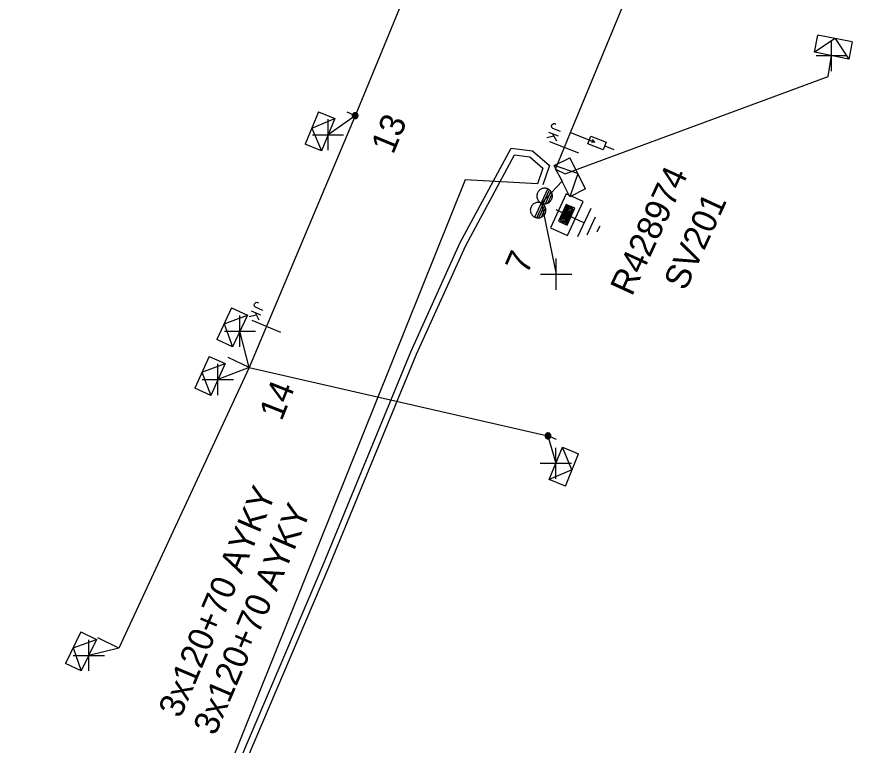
# Model space of a CAD drawing. Extents: x -540247 to -537390, y -1183887 to -1180355.
# Drawn here: x -537727.87 to -537694.26, y -1180525.39 to -1180496.15 of the extents above; entities that cross this region are included whole.
import ezdxf

# ---------------------------------------------------------------- set-up
doc = ezdxf.new("R2010")
doc.units = 0
for name, color, linetype in [('Vrstva 1', 7, 'Continuous'), ('Vrstva 13', 7, 'Continuous'), ('Vrstva 14', 7, 'Continuous'), ('Vrstva 15', 7, 'Continuous'), ('Vrstva 16', 7, 'Continuous'), ('Vrstva 18', 7, 'Continuous'), ('Vrstva 2', 7, 'Continuous'), ('Vrstva 28', 7, 'Continuous'), ('Vrstva 29', 7, 'Continuous'), ('Vrstva 30', 7, 'Continuous'), ('Vrstva 31', 7, 'Continuous'), ('Vrstva 34', 7, 'Continuous'), ('Vrstva 4', 7, 'Continuous'), ('Vrstva 5', 7, 'Continuous'), ('Vrstva 50', 7, 'Continuous'), ('Vrstva 52', 7, 'Continuous'), ('Vrstva 54', 7, 'Continuous'), ('Vrstva 6', 7, 'Continuous'), ('Vrstva 8', 7, 'Continuous'), ('Vrstva 9', 7, 'Continuous')]:
    doc.layers.add(name, color=color, linetype=linetype)

# ---------------------------------------------------------------- blocks, each defined once
blk = doc.blocks.new('NN450')
at = {"layer": 'Vrstva 2'}
for points in [[(0, 0), (-0.003, 0.065), (-0.013, 0.13), (-0.031, 0.193), (-0.054, 0.254), (-0.084, 0.312), (-0.119, 0.367), (-0.161, 0.418), (-0.207, 0.464), (-0.258, 0.505), (-0.313, 0.541), (-0.371, 0.571), (-0.432, 0.594), (-0.495, 0.611), (-0.559, 0.621), (-0.625, 0.625), (-0.69, 0.621), (-0.755, 0.611), (-0.818, 0.594), (-0.879, 0.571), (-0.938, 0.541), (-0.992, 0.505), (-1.043, 0.464), (-1.089, 0.418), (-1.13, 0.367), (-1.166, 0.312), (-1.196, 0.254), (-1.219, 0.193), (-1.236, 0.13), (-1.246, 0.065), (-1.25, 0), (-1.246, -0.066), (-1.236, -0.13), (-1.219, -0.193), (-1.196, -0.255), (-1.166, -0.313), (-1.13, -0.368), (-1.089, -0.419), (-1.043, -0.465), (-0.992, -0.506), (-0.937, -0.542), (-0.879, -0.571), (-0.818, -0.595), (-0.755, -0.612), (-0.69, -0.622), (-0.625, -0.625), (-0.559, -0.622), (-0.495, -0.612), (-0.432, -0.595), (-0.37, -0.571), (-0.312, -0.542), (-0.258, -0.506), (-0.207, -0.465), (-0.161, -0.419), (-0.119, -0.368), (-0.084, -0.313), (-0.054, -0.254), (-0.031, -0.193), (-0.013, -0.13), (-0.003, -0.066), (0, 0)], [(1.25, 0), (1.247, 0.065), (1.237, 0.13), (1.219, 0.193), (1.196, 0.254), (1.166, 0.312), (1.131, 0.367), (1.089, 0.418), (1.043, 0.464), (0.992, 0.505), (0.937, 0.541), (0.879, 0.571), (0.818, 0.594), (0.755, 0.611), (0.691, 0.621), (0.625, 0.625), (0.56, 0.621), (0.495, 0.611), (0.432, 0.594), (0.371, 0.571), (0.312, 0.541), (0.258, 0.505), (0.207, 0.464), (0.161, 0.418), (0.12, 0.367), (0.084, 0.312), (0.054, 0.254), (0.031, 0.193), (0.014, 0.13), (0.004, 0.065), (0, 0), (0.004, -0.066), (0.014, -0.13), (0.031, -0.193), (0.054, -0.255), (0.084, -0.313), (0.12, -0.368), (0.161, -0.419), (0.207, -0.465), (0.258, -0.506), (0.313, -0.542), (0.371, -0.571), (0.432, -0.595), (0.495, -0.612), (0.56, -0.622), (0.625, -0.625), (0.691, -0.622), (0.755, -0.612), (0.818, -0.595), (0.88, -0.571), (0.938, -0.542), (0.992, -0.506), (1.043, -0.465), (1.089, -0.419), (1.131, -0.368), (1.166, -0.313), (1.196, -0.254), (1.219, -0.193), (1.237, -0.13), (1.247, -0.066), (1.25, 0)], [(-1.25, 0), (1.25, 0)], [(-1.23, -0.158), (-0.02, -0.158)], [(-1.161, -0.315), (-0.088, -0.315)], [(-1.033, -0.473), (-0.216, -0.473)], [(0.02, -0.158), (1.23, -0.158)], [(0.089, -0.315), (1.162, -0.315)], [(0.217, -0.473), (1.034, -0.473)]]:
    blk.add_lwpolyline(points, dxfattribs=at)
blk = doc.blocks.new('NN840')
at = {"layer": 'Vrstva 15'}
for points in [[(0.003, 0.619), (0.003, -0.631)], [(-0.745, -0.71), (-0.745, -0.66)], [(-0.538, -0.385), (-0.538, -0.71)], [(-0.332, -0.385), (-0.332, -0.798)], [(-0.332, -0.641), (-0.125, -0.385)], [(-0.263, -0.557), (-0.091, -0.798)], [(-0.73, -0.764), (-0.745, -0.71)], [(-0.657, -0.798), (-0.73, -0.764)], [(-0.627, -0.798), (-0.657, -0.798)], [(-0.558, -0.764), (-0.627, -0.798)], [(-0.538, -0.71), (-0.558, -0.764)]]:
    blk.add_lwpolyline(points, dxfattribs=at)
blk = doc.blocks.new('NN800')
at = {"layer": 'Vrstva 1'}
for points in [[(-0.442, 0.442), (0.442, -0.442)], [(-0.442, -0.442), (0.442, 0.442)]]:
    blk.add_lwpolyline(points, dxfattribs=at)
blk = doc.blocks.new('NN820')
at = {"layer": 'Vrstva 13'}
for points in [[(-0.003, 0.004), (-0.003, -1.049)], [(-0.165, -0.813), (0.165, -0.813)], [(-0.165, -1.473), (-0.165, -0.813)], [(-0.003, -1.049), (-0.062, -0.926)], [(-0.003, -1.049), (0.057, -0.926)], [(0.165, -0.813), (0.165, -1.473)], [(0.165, -1.473), (-0.165, -1.473)], [(-0.003, -1.473), (-0.003, -1.871)]]:
    blk.add_lwpolyline(points, dxfattribs=at)
blk = doc.blocks.new('NN620')
at = {"layer": 'Vrstva 8'}
for points in [[(0.752, 0.004), (-0.748, 0.004)], [(-0.748, 0.004), (-0.748, -0.746)], [(0.752, -0.746), (0.752, 0.004)], [(0.368, -0.18), (-0.376, -0.18)], [(-0.376, -0.18), (-0.376, -0.558)], [(0.321, -0.227), (-0.329, -0.227)], [(-0.329, -0.227), (-0.329, -0.51)], [(0.274, -0.274), (-0.281, -0.274)], [(-0.281, -0.274), (-0.281, -0.463)], [(0.227, -0.321), (-0.234, -0.321)], [(-0.234, -0.321), (-0.234, -0.416)], [(0.227, -0.416), (0.227, -0.321)], [(0.274, -0.463), (0.274, -0.274)], [(0.321, -0.51), (0.321, -0.227)], [(0.368, -0.558), (0.368, -0.18)], [(-0.376, -0.558), (0.368, -0.558)], [(-0.329, -0.51), (0.321, -0.51)], [(-0.281, -0.463), (0.274, -0.463)], [(-0.234, -0.416), (0.227, -0.416)], [(-0.193, -0.369), (0.185, -0.369)], [(-0.748, -0.746), (0.752, -0.746)]]:
    blk.add_lwpolyline(points, dxfattribs=at)
blk = doc.blocks.new('NN630')
at = {"layer": 'Vrstva 9'}
for points in [[(-0.003, -0.7), (-0.703, 0)], [(-0.703, -0.7), (-0.703, 0), (0.697, 0), (0.697, -0.7)], [(-0.003, -0.7), (0.697, 0)], [(-0.703, -0.7), (0.697, -0.7)]]:
    blk.add_lwpolyline(points, dxfattribs=at)
blk = doc.blocks.new('NN810')
at = {"layer": 'Vrstva 14'}
for points in [[(0.004, -0.64), (0.004, -1.89)], [(0.629, -1.89), (-0.621, -1.89)], [(0.388, -2.2), (-0.399, -2.2)], [(0.004, -2.515), (-0.124, -2.515)], [(0.137, -2.515), (0.004, -2.515)]]:
    blk.add_lwpolyline(points, dxfattribs=at)
blk = doc.blocks.new('NN500')
at = {"layer": 'Vrstva 2'}
for points in [[(-0.001, -0.235), (0.023, -0.234), (0.048, -0.23), (0.071, -0.224), (0.094, -0.215), (0.116, -0.204), (0.137, -0.191), (0.156, -0.175), (0.173, -0.158), (0.189, -0.139), (0.202, -0.118), (0.213, -0.096), (0.222, -0.073), (0.229, -0.049), (0.232, -0.025), (0.234, 0), (0.232, 0.024), (0.229, 0.048), (0.222, 0.072), (0.213, 0.095), (0.202, 0.117), (0.189, 0.138), (0.173, 0.157), (0.156, 0.174), (0.137, 0.19), (0.116, 0.203), (0.094, 0.214), (0.071, 0.223), (0.048, 0.229), (0.023, 0.233), (-0.001, 0.235), (-0.026, 0.233), (-0.05, 0.229), (-0.074, 0.223), (-0.097, 0.214), (-0.119, 0.203), (-0.139, 0.19), (-0.158, 0.174), (-0.176, 0.157), (-0.191, 0.138), (-0.205, 0.117), (-0.216, 0.095), (-0.225, 0.072), (-0.231, 0.048), (-0.235, 0.024), (-0.236, 0), (-0.235, -0.025), (-0.231, -0.049), (-0.225, -0.073), (-0.216, -0.096), (-0.205, -0.118), (-0.191, -0.139), (-0.176, -0.158), (-0.158, -0.175), (-0.139, -0.191), (-0.119, -0.204), (-0.097, -0.215), (-0.074, -0.224), (-0.05, -0.23), (-0.026, -0.234), (-0.001, -0.235)], [(-0.001, -0.235), (0.023, -0.234), (0.048, -0.23), (0.071, -0.224), (0.094, -0.215), (0.116, -0.204), (0.137, -0.191), (0.156, -0.175), (0.173, -0.158), (0.189, -0.139), (0.202, -0.118), (0.213, -0.096), (0.222, -0.073), (0.229, -0.049), (0.232, -0.025), (0.234, 0), (0.232, 0.024), (0.229, 0.048), (0.222, 0.072), (0.213, 0.095), (0.202, 0.117), (0.189, 0.138), (0.173, 0.157), (0.156, 0.174), (0.137, 0.19), (0.116, 0.203), (0.094, 0.214), (0.071, 0.223), (0.048, 0.229), (0.023, 0.233), (-0.001, 0.235), (-0.026, 0.233), (-0.05, 0.229), (-0.074, 0.223), (-0.097, 0.214), (-0.119, 0.203), (-0.139, 0.19), (-0.158, 0.174), (-0.176, 0.157), (-0.191, 0.138), (-0.205, 0.117), (-0.216, 0.095), (-0.225, 0.072), (-0.231, 0.048), (-0.235, 0.024), (-0.236, 0), (-0.235, -0.025), (-0.231, -0.049), (-0.225, -0.073), (-0.216, -0.096), (-0.205, -0.118), (-0.191, -0.139), (-0.176, -0.158), (-0.158, -0.175), (-0.139, -0.191), (-0.119, -0.204), (-0.097, -0.215), (-0.074, -0.224), (-0.05, -0.23), (-0.026, -0.234), (-0.001, -0.235)], [(-0.001, -0.206), (0.02, -0.205), (0.041, -0.201), (0.062, -0.196), (0.082, -0.188), (0.101, -0.178), (0.12, -0.167), (0.136, -0.153), (0.151, -0.138), (0.165, -0.121), (0.177, -0.103), (0.186, -0.084), (0.194, -0.064), (0.2, -0.043), (0.203, -0.022), (0.204, 0), (0.203, 0.021), (0.2, 0.042), (0.194, 0.063), (0.186, 0.083), (0.177, 0.102), (0.165, 0.12), (0.151, 0.137), (0.136, 0.152), (0.12, 0.166), (0.101, 0.177), (0.082, 0.187), (0.062, 0.195), (0.041, 0.2), (0.02, 0.204), (-0.001, 0.205), (-0.023, 0.204), (-0.044, 0.2), (-0.065, 0.195), (-0.085, 0.187), (-0.104, 0.177), (-0.122, 0.166), (-0.139, 0.152), (-0.154, 0.137), (-0.167, 0.12), (-0.179, 0.102), (-0.189, 0.083), (-0.197, 0.063), (-0.202, 0.042), (-0.205, 0.021), (-0.207, 0), (-0.205, -0.022), (-0.202, -0.043), (-0.197, -0.064), (-0.189, -0.084), (-0.179, -0.103), (-0.167, -0.121), (-0.154, -0.138), (-0.139, -0.153), (-0.122, -0.167), (-0.104, -0.178), (-0.085, -0.188), (-0.065, -0.196), (-0.044, -0.201), (-0.023, -0.205), (-0.001, -0.206)], [(-0.001, -0.176), (0.017, -0.175), (0.035, -0.172), (0.053, -0.168), (0.07, -0.161), (0.087, -0.153), (0.102, -0.143), (0.116, -0.131), (0.129, -0.118), (0.141, -0.104), (0.151, -0.088), (0.159, -0.072), (0.166, -0.055), (0.171, -0.037), (0.174, -0.019), (0.175, 0), (0.174, 0.018), (0.171, 0.036), (0.166, 0.054), (0.159, 0.071), (0.151, 0.087), (0.141, 0.103), (0.129, 0.117), (0.116, 0.13), (0.102, 0.142), (0.087, 0.152), (0.07, 0.16), (0.053, 0.167), (0.035, 0.172), (0.017, 0.174), (-0.001, 0.175), (-0.02, 0.174), (-0.038, 0.172), (-0.056, 0.167), (-0.073, 0.16), (-0.089, 0.152), (-0.105, 0.142), (-0.119, 0.13), (-0.132, 0.117), (-0.143, 0.103), (-0.153, 0.087), (-0.162, 0.071), (-0.168, 0.054), (-0.173, 0.036), (-0.176, 0.018), (-0.177, 0), (-0.176, -0.019), (-0.173, -0.037), (-0.168, -0.055), (-0.162, -0.072), (-0.153, -0.088), (-0.143, -0.104), (-0.132, -0.118), (-0.119, -0.131), (-0.105, -0.143), (-0.089, -0.153), (-0.073, -0.161), (-0.056, -0.168), (-0.038, -0.172), (-0.02, -0.175), (-0.001, -0.176)], [(-0.001, -0.147), (0.014, -0.146), (0.029, -0.143), (0.044, -0.139), (0.058, -0.134), (0.072, -0.127), (0.085, -0.119), (0.097, -0.109), (0.107, -0.098), (0.117, -0.086), (0.125, -0.073), (0.132, -0.06), (0.138, -0.046), (0.142, -0.031), (0.144, -0.016), (0.145, 0), (0.144, 0.015), (0.142, 0.03), (0.138, 0.045), (0.132, 0.059), (0.125, 0.073), (0.117, 0.086), (0.107, 0.097), (0.097, 0.108), (0.085, 0.118), (0.072, 0.126), (0.058, 0.133), (0.044, 0.139), (0.029, 0.143), (0.014, 0.145), (-0.001, 0.146), (-0.017, 0.145), (-0.032, 0.143), (-0.046, 0.139), (-0.061, 0.133), (-0.074, 0.126), (-0.087, 0.118), (-0.099, 0.108), (-0.11, 0.097), (-0.119, 0.086), (-0.128, 0.073), (-0.135, 0.059), (-0.14, 0.045), (-0.144, 0.03), (-0.147, 0.015), (-0.147, 0), (-0.147, -0.016), (-0.144, -0.031), (-0.14, -0.046), (-0.135, -0.06), (-0.128, -0.073), (-0.119, -0.086), (-0.11, -0.098), (-0.099, -0.109), (-0.087, -0.119), (-0.074, -0.127), (-0.061, -0.134), (-0.046, -0.139), (-0.032, -0.143), (-0.017, -0.146), (-0.001, -0.147)], [(-0.001, -0.117), (0.011, -0.116), (0.023, -0.114), (0.035, -0.111), (0.046, -0.107), (0.057, -0.101), (0.067, -0.095), (0.077, -0.087), (0.085, -0.078), (0.093, -0.069), (0.1, -0.059), (0.105, -0.048), (0.11, -0.036), (0.113, -0.025), (0.115, -0.013), (0.115, 0), (0.115, 0.012), (0.113, 0.024), (0.11, 0.036), (0.105, 0.047), (0.1, 0.058), (0.093, 0.068), (0.085, 0.078), (0.077, 0.086), (0.067, 0.094), (0.057, 0.101), (0.046, 0.106), (0.035, 0.11), (0.023, 0.114), (0.011, 0.116), (-0.001, 0.116), (-0.013, 0.116), (-0.025, 0.114), (-0.037, 0.11), (-0.049, 0.106), (-0.059, 0.101), (-0.07, 0.094), (-0.079, 0.086), (-0.088, 0.078), (-0.096, 0.068), (-0.102, 0.058), (-0.108, 0.047), (-0.112, 0.036), (-0.115, 0.024), (-0.117, 0.012), (-0.118, 0), (-0.117, -0.013), (-0.115, -0.025), (-0.112, -0.036), (-0.108, -0.048), (-0.102, -0.059), (-0.096, -0.069), (-0.088, -0.078), (-0.079, -0.087), (-0.07, -0.095), (-0.059, -0.101), (-0.049, -0.107), (-0.037, -0.111), (-0.025, -0.114), (-0.013, -0.116), (-0.001, -0.117)], [(-0.001, -0.087), (0.008, -0.087), (0.017, -0.085), (0.026, -0.083), (0.034, -0.08), (0.042, -0.076), (0.05, -0.071), (0.057, -0.065), (0.063, -0.059), (0.069, -0.051), (0.074, -0.044), (0.078, -0.036), (0.081, -0.027), (0.084, -0.019), (0.085, -0.01), (0.086, 0), (0.085, 0.009), (0.084, 0.018), (0.081, 0.026), (0.078, 0.035), (0.074, 0.043), (0.069, 0.051), (0.063, 0.058), (0.057, 0.064), (0.05, 0.07), (0.042, 0.075), (0.034, 0.079), (0.026, 0.082), (0.017, 0.085), (0.008, 0.086), (-0.001, 0.087), (-0.01, 0.086), (-0.019, 0.085), (-0.028, 0.082), (-0.037, 0.079), (-0.045, 0.075), (-0.052, 0.07), (-0.059, 0.064), (-0.066, 0.058), (-0.072, 0.051), (-0.077, 0.043), (-0.081, 0.035), (-0.084, 0.026), (-0.086, 0.018), (-0.088, 0.009), (-0.088, 0), (-0.088, -0.01), (-0.086, -0.019), (-0.084, -0.027), (-0.081, -0.036), (-0.077, -0.044), (-0.072, -0.052), (-0.066, -0.059), (-0.059, -0.065), (-0.052, -0.071), (-0.045, -0.076), (-0.037, -0.08), (-0.028, -0.083), (-0.019, -0.085), (-0.01, -0.087), (-0.001, -0.087)], [(-0.001, -0.058), (0.005, -0.057), (0.011, -0.056), (0.016, -0.055), (0.022, -0.053), (0.027, -0.05), (0.032, -0.047), (0.037, -0.043), (0.041, -0.039), (0.045, -0.034), (0.048, -0.029), (0.051, -0.024), (0.053, -0.018), (0.055, -0.012), (0.056, -0.006), (0.056, 0), (0.056, 0.006), (0.055, 0.011), (0.053, 0.017), (0.051, 0.023), (0.048, 0.028), (0.045, 0.033), (0.041, 0.038), (0.037, 0.042), (0.032, 0.046), (0.027, 0.049), (0.022, 0.052), (0.016, 0.054), (0.011, 0.056), (0.005, 0.057), (-0.001, 0.057), (-0.007, 0.057), (-0.013, 0.056), (-0.019, 0.054), (-0.025, 0.052), (-0.03, 0.049), (-0.035, 0.046), (-0.04, 0.042), (-0.044, 0.038), (-0.048, 0.033), (-0.051, 0.028), (-0.054, 0.023), (-0.056, 0.017), (-0.057, 0.011), (-0.058, 0.006), (-0.059, 0), (-0.058, -0.006), (-0.057, -0.012), (-0.056, -0.018), (-0.054, -0.024), (-0.051, -0.029), (-0.048, -0.034), (-0.044, -0.039), (-0.04, -0.043), (-0.035, -0.047), (-0.03, -0.05), (-0.025, -0.053), (-0.019, -0.055), (-0.013, -0.056), (-0.007, -0.057), (-0.001, -0.058)], [(-0.001, -0.028), (0.002, -0.028), (0.005, -0.028), (0.007, -0.027), (0.01, -0.026), (0.013, -0.024), (0.015, -0.023), (0.017, -0.021), (0.019, -0.019), (0.021, -0.017), (0.023, -0.014), (0.024, -0.012), (0.025, -0.009), (0.026, -0.006), (0.026, -0.003), (0.027, 0), (0.026, 0.002), (0.026, 0.005), (0.025, 0.008), (0.024, 0.011), (0.023, 0.013), (0.021, 0.016), (0.019, 0.018), (0.017, 0.02), (0.015, 0.022), (0.013, 0.024), (0.01, 0.025), (0.007, 0.026), (0.005, 0.027), (0.002, 0.027), (-0.001, 0.027), (-0.004, 0.027), (-0.007, 0.027), (-0.01, 0.026), (-0.012, 0.025), (-0.015, 0.024), (-0.018, 0.022), (-0.02, 0.02), (-0.022, 0.018), (-0.024, 0.016), (-0.025, 0.013), (-0.027, 0.011), (-0.028, 0.008), (-0.028, 0.005), (-0.029, 0.002), (-0.029, 0), (-0.029, -0.003), (-0.028, -0.006), (-0.028, -0.009), (-0.027, -0.012), (-0.025, -0.014), (-0.024, -0.017), (-0.022, -0.019), (-0.02, -0.021), (-0.018, -0.023), (-0.015, -0.024), (-0.012, -0.026), (-0.01, -0.027), (-0.007, -0.028), (-0.004, -0.028), (-0.001, -0.028)], [(0.234, 0), (0.704, 0)]]:
    blk.add_lwpolyline(points, dxfattribs=at)
blk = doc.blocks.new('NN510')
at = {"layer": 'Vrstva 2'}
blk.add_lwpolyline([(0.001, 0.002), (0.001, 0.939)], dxfattribs=at)

msp = doc.modelspace()

# ---------------------------------------------------------------- linework, layer by layer
at = {"layer": 'Vrstva 4'}
msp.add_lwpolyline([(-537718.536, -1180510.223), (-537706.55, -1180512.97), (-537706.235, -1180514.068)], dxfattribs=at)
at = {"layer": 'Vrstva 5'}
for points in [[(-537734.68, -1180524.19), (-537734.74, -1180524.45), (-537732.42, -1180525.38), (-537728.3, -1180526.32), (-537725.94, -1180526.78), (-537719.916, -1180528.443), (-537719.145, -1180526.532), (-537715.575, -1180518.142), (-537712.055, -1180509.59), (-537710.072, -1180505.214), (-537708.029, -1180501.425), (-537707.177, -1180501.531), (-537706.489, -1180502.117), (-537706.751, -1180502.897)], [(-537694.259, -1180538.2), (-537694.383, -1180538.509), (-537694.85, -1180538.67), (-537700.14, -1180535.98), (-537704.89, -1180534.15), (-537714.67, -1180530.95), (-537719.56, -1180529.24), (-537719.684, -1180528.537), (-537718.915, -1180526.628), (-537715.345, -1180518.238), (-537711.825, -1180509.69), (-537709.848, -1180505.326), (-537707.891, -1180501.695), (-537707.283, -1180501.769), (-537706.751, -1180502.223), (-537706.972, -1180502.847)]]:
    msp.add_lwpolyline(points, dxfattribs=at)
at = {"layer": 'Vrstva 50'}
for points in [[(-537695.509, -1180475.222), (-537708.786, -1180486.772), (-537714.289, -1180500.117), (-537718.536, -1180510.223)], [(-537706.255, -1180502.27), (-537705.642, -1180500.791), (-537695.184, -1180475.522)]]:
    msp.add_lwpolyline(points, dxfattribs=at)
at = {"layer": 'Vrstva 52'}
for points in [[(-537706.255, -1180502.27), (-537705.862, -1180502.457), (-537705.264, -1180502.227), (-537695.308, -1180498.547), (-537695.168, -1180497.706)], [(-537706.255, -1180502.27), (-537705.987, -1180502.739), (-537706.815, -1180503.624), (-537706.223, -1180506.478)], [(-537706.972, -1180502.847), (-537709.876, -1180502.687), (-537719.944, -1180527.767), (-537711.939, -1180530.834), (-537711.509, -1180530.148)]]:
    msp.add_lwpolyline(points, dxfattribs=at)
at = {"layer": 'Vrstva 54'}
for points in [[(-537714.289, -1180500.117), (-537715.376, -1180500.882)], [(-537718.536, -1180510.223), (-537718.913, -1180508.765)], [(-537718.536, -1180510.223), (-537719.799, -1180510.708)]]:
    msp.add_lwpolyline(points, dxfattribs=at)
at = {"layer": 'Vrstva 8'}
msp.add_lwpolyline([(-537718.536, -1180510.223), (-537723.775, -1180521.485), (-537724.975, -1180521.779)], dxfattribs=at)

# ---------------------------------------------------------------- block references
at = {"layer": 'Vrstva 13'}
for name, p, xscale, yscale, rotation in [('NN500', (-537714.289, -1180500.117), 0.5000000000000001, 0.5, 157.57999991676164), ('NN450', (-537706.816, -1180503.625), 0.5, 0.49999999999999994, 65.39917218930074), ('NN500', (-537706.55, -1180512.97), 0.49999999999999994, 0.5000000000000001, -21.98999987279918)]:
    msp.add_blockref(name, p, dxfattribs=dict(at, xscale=xscale, yscale=yscale, rotation=rotation))
for p, rotation in [((-537718.536, -1180510.224), 64.97272221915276), ((-537723.774, -1180521.486), 64.16566394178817)]:
    msp.add_blockref('NN510', p, dxfattribs=dict(at, rotation=rotation))
at = {"layer": 'Vrstva 15', "rotation": 65.19926120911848}
msp.add_blockref('NN810', (-537706.815, -1180503.624), dxfattribs=at)
at = {"layer": 'Vrstva 16', "rotation": 68.49706113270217}
msp.add_blockref('NN820', (-537705.642, -1180500.791), dxfattribs=at)
at = {"layer": 'Vrstva 18'}
for p, rotation in [((-537705.891, -1180501.39), -111.5029389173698), ((-537717.845, -1180508.578), -112.79435559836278)]:
    msp.add_blockref('NN840', p, dxfattribs=dict(at, rotation=rotation))
at = {"layer": 'Vrstva 28', "rotation": 65.32699999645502}
msp.add_blockref('NN620', (-537706.133, -1180503.937), dxfattribs=at)
at = {"layer": 'Vrstva 31'}
for p, rotation in [((-537695.168, -1180497.706), 168.68557226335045), ((-537715.376, -1180500.882), -112.42006109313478), ((-537705.987, -1180502.739), 116.28159717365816), ((-537718.913, -1180508.765), -115.02727778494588), ((-537719.799, -1180510.708), -114.1805888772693), ((-537706.235, -1180514.068), 68.01026113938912), ((-537724.975, -1180521.779), -115.83433617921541)]:
    msp.add_blockref('NN630', p, dxfattribs=dict(at, rotation=rotation))
at = {"layer": 'Vrstva 34'}
for p, rotation in [((-537695.168, -1180497.706), 44.99999995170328), ((-537715.376, -1180500.882), 45), ((-537706.223, -1180506.478), 45), ((-537718.913, -1180508.765), 44.99999995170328), ((-537719.799, -1180510.708), 45), ((-537706.235, -1180514.068), 45), ((-537724.975, -1180521.779), 45)]:
    msp.add_blockref('NN800', p, dxfattribs=dict(at, rotation=rotation))

# ---------------------------------------------------------------- texts
at = {"layer": 'Vrstva 14'}
for s, rotation, p in [('13', 67.484, (-537712.765, -1180501.706)), ('7', 66.193, (-537707.391, -1180506.524)), ('14', 68.448, (-537717.239, -1180512.406))]:
    msp.add_text(s, height=1, rotation=rotation, dxfattribs=at).set_placement(p)
at = {"layer": 'Vrstva 29'}
msp.add_text('R428974', height=1, rotation=65.327, dxfattribs=at).set_placement((-537703.182, -1180507.4))
at = {"layer": 'Vrstva 30'}
msp.add_text('SV201', height=1, rotation=65.327, dxfattribs=at).set_placement((-537701.033, -1180507.185))
at = {"layer": 'Vrstva 6'}
for p in [(-537721.302, -1180524.338), (-537719.905, -1180525.037)]:
    msp.add_text('3x120+70 AYKY', height=1, rotation=66.95, dxfattribs=at).set_placement(p)

doc.saveas('drawing.dxf')
